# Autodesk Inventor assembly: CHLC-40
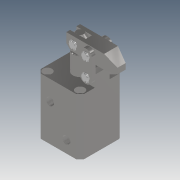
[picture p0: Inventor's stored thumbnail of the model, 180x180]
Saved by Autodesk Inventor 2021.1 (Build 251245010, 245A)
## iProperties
Created: 2019-04
Part Number: CHLC-40
Description: STEP AP214
Document SubType Name: Assembly
Designer: user
Sending System: SolidWorks 2016
Preprocessor: SwSTEP 2.0
Title: CHLC-40.STEP
Revision Number: ÈÎºÎ
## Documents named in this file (8)
- D:\Vault_2016\Projekty\Clamptek\Hydraulic\CHLC\CHLC-40\Inventor\CHLC-40\CHLC-40.iam
- D:\Vault_2016\Projekty\Clamptek\Hydraulic\CHLC\CHLC-40\Inventor\CHLC-40\CHLC-40-05.ipt
- D:\Vault_2016\Projekty\Clamptek\Hydraulic\CHLC\CHLC-40\Inventor\CHLC-40\CHLC-40-08.ipt
- D:\Vault_2016\Projekty\Clamptek\Hydraulic\CHLC\CHLC-40\Inventor\CHLC-40\CHLC-40-01.ipt
- D:\Vault_2016\Projekty\Clamptek\Hydraulic\CHLC\CHLC-40\Inventor\CHLC-40\CHLC-40-03.ipt
- D:\Vault_2016\Projekty\Clamptek\Hydraulic\CHLC\CHLC-40\Inventor\CHLC-40\CHLC-40-02.ipt
- D:\Vault_2016\Projekty\Clamptek\Hydraulic\CHLC\CHLC-40\Inventor\CHLC-40\CHLC-40-04.ipt
- D:\Vault_2016\Projekty\Clamptek\Hydraulic\CHLC\CHLC-40\Inventor\CHLC-40\CHLC-40-06.ipt
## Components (14 placed, 14 different names)
1. CHLC-40-05_1
2. CHLC-40-08_2
3. CHLC-40-01_3
4. CHLC-40-03_4
5. CHLC-40-03_5
6. CHLC-40-02_6
7. CHLC-40-02_7
8. CHLC-40-04_8
9. CHLC-40-06_9
10. CHLC-40-06_10
11. CHLC-40-06_11
12. CHLC-40-06_12
13. CHLC-40-06_13
14. CHLC-40-06_14
